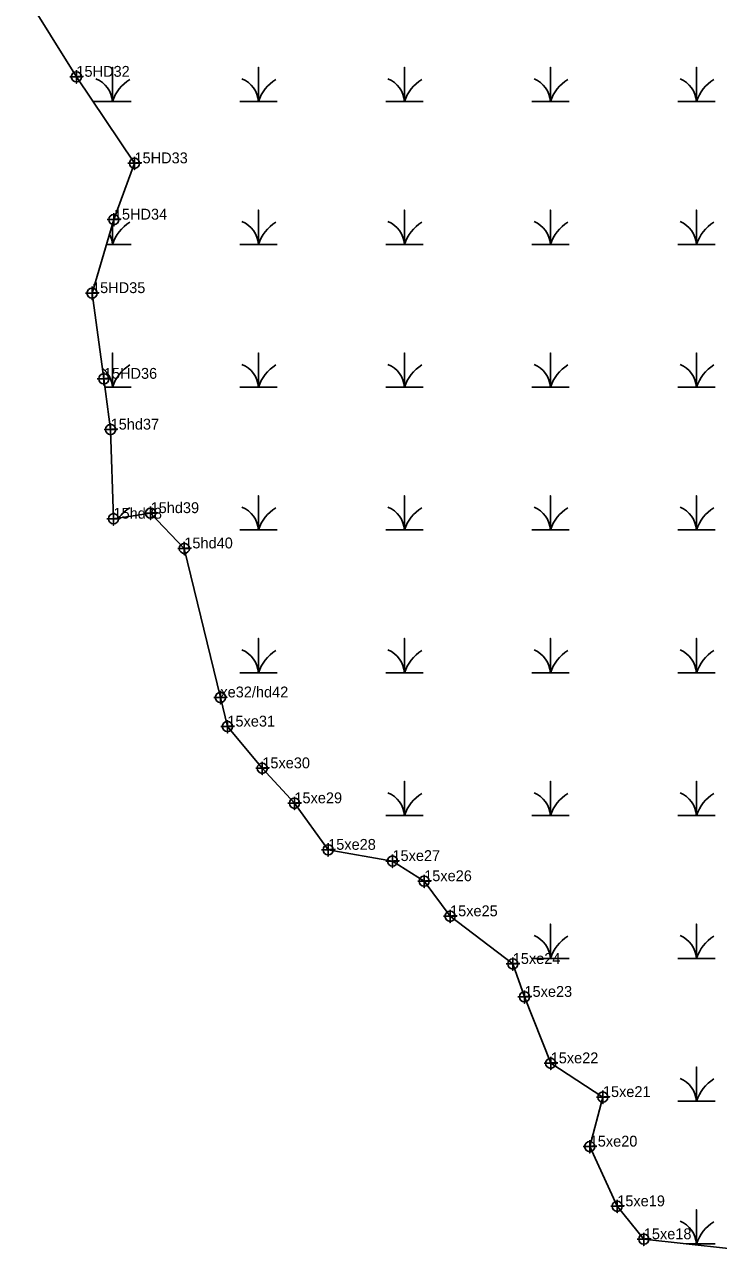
# Model space of a CAD drawing. Extents: x 2071991 to 2268989, y 436479 to 469629.
# Drawn here: x 2267215 to 2267534, y 443490 to 444054 of the extents above; entities that cross this region are included whole.
import ezdxf

# ---------------------------------------------------------------- set-up
doc = ezdxf.new("R2010")
doc.units = 0
for name, color, linetype in [('Exist Environmental Wetland Boundary', 7, 'Continuous'), ('Exist Environmental Wetland Boundary Cogo Comment', 7, 'Continuous'), ('Exist Environmental Wetland Boundary Cogo Point CELL', 7, 'Continuous'), ('Exist Hydro Swamp or Marsh', 7, 'Continuous')]:
    doc.layers.add(name, color=color, linetype=linetype)

msp = doc.modelspace()

# ---------------------------------------------------------------- linework, layer by layer
at = {"layer": 'Exist Environmental Wetland Boundary'}
for points in [[(2267254.71, 443867.46), (2267251.59, 443890.85), (2267246.15, 443930.33), (2267256.19, 443964.18), (2267265.69, 443990.12), (2267238.96, 444029.98), (2267215.07, 444068.53)], [(2267539.01, 443490.2), (2267500.11, 443494.48), (2267487.88, 443509.65), (2267475.21, 443537.15), (2267481.28, 443559.98), (2267457.24, 443575.52), (2267445.19, 443606.13), (2267439.79, 443621.29), (2267410.94, 443643.26), (2267399.03, 443659.42), (2267384.42, 443668.71), (2267354.83, 443673.87), (2267339.3, 443695.32), (2267324.52, 443711.42), (2267308.45, 443730.65), (2267305.23, 443744.08), (2267288.63, 443812.72), (2267273.11, 443828.98), (2267256.02, 443826.4), (2267254.71, 443867.46)]]:
    msp.add_lwpolyline(points, dxfattribs=at)
at = {"layer": 'Exist Environmental Wetland Boundary Cogo Point CELL'}
for points in [[(2267238.96, 444032.98), (2267238.96, 444026.98), (2267238.96, 444029.98), (2267241.96, 444029.98), (2267235.96, 444029.98)], [(2267265.69, 443993.12), (2267265.69, 443987.12), (2267265.69, 443990.12), (2267268.69, 443990.12), (2267262.69, 443990.12)], [(2267256.19, 443967.18), (2267256.19, 443961.18), (2267256.19, 443964.18), (2267259.19, 443964.18), (2267253.19, 443964.18)], [(2267246.15, 443933.33), (2267246.15, 443927.33), (2267246.15, 443930.33), (2267249.15, 443930.33), (2267243.15, 443930.33)], [(2267251.59, 443893.85), (2267251.59, 443887.85), (2267251.59, 443890.85), (2267254.59, 443890.85), (2267248.59, 443890.85)], [(2267254.71, 443870.46), (2267254.71, 443864.46), (2267254.71, 443867.46), (2267257.71, 443867.46), (2267251.71, 443867.46)], [(2267273.11, 443831.98), (2267273.11, 443825.98), (2267273.11, 443828.98), (2267276.11, 443828.98), (2267270.11, 443828.98)], [(2267256.02, 443829.4), (2267256.02, 443823.4), (2267256.02, 443826.4), (2267259.02, 443826.4), (2267253.02, 443826.4)], [(2267288.63, 443815.72), (2267288.63, 443809.72), (2267288.63, 443812.72), (2267291.63, 443812.72), (2267285.63, 443812.72)], [(2267305.23, 443747.08), (2267305.23, 443741.08), (2267305.23, 443744.08), (2267308.23, 443744.08), (2267302.23, 443744.08)], [(2267308.45, 443733.65), (2267308.45, 443727.65), (2267308.45, 443730.65), (2267311.45, 443730.65), (2267305.45, 443730.65)], [(2267324.52, 443714.42), (2267324.52, 443708.42), (2267324.52, 443711.42), (2267327.52, 443711.42), (2267321.52, 443711.42)], [(2267339.3, 443698.32), (2267339.3, 443692.32), (2267339.3, 443695.32), (2267342.3, 443695.32), (2267336.3, 443695.32)], [(2267354.83, 443676.87), (2267354.83, 443670.87), (2267354.83, 443673.87), (2267357.83, 443673.87), (2267351.83, 443673.87)], [(2267384.42, 443671.71), (2267384.42, 443665.71), (2267384.42, 443668.71), (2267387.42, 443668.71), (2267381.42, 443668.71)], [(2267399.03, 443662.42), (2267399.03, 443656.42), (2267399.03, 443659.42), (2267402.03, 443659.42), (2267396.03, 443659.42)], [(2267410.94, 443646.26), (2267410.94, 443640.26), (2267410.94, 443643.26), (2267413.94, 443643.26), (2267407.94, 443643.26)], [(2267439.79, 443624.29), (2267439.79, 443618.29), (2267439.79, 443621.29), (2267442.79, 443621.29), (2267436.79, 443621.29)], [(2267445.19, 443609.13), (2267445.19, 443603.13), (2267445.19, 443606.13), (2267448.19, 443606.13), (2267442.19, 443606.13)], [(2267457.24, 443578.52), (2267457.24, 443572.52), (2267457.24, 443575.52), (2267460.24, 443575.52), (2267454.24, 443575.52)], [(2267481.28, 443562.98), (2267481.28, 443556.98), (2267481.28, 443559.98), (2267484.28, 443559.98), (2267478.28, 443559.98)], [(2267475.21, 443540.15), (2267475.21, 443534.15), (2267475.21, 443537.15), (2267478.21, 443537.15), (2267472.21, 443537.15)], [(2267487.88, 443512.65), (2267487.88, 443506.65), (2267487.88, 443509.65), (2267490.88, 443509.65), (2267484.88, 443509.65)], [(2267500.11, 443497.48), (2267500.11, 443491.48), (2267500.11, 443494.48), (2267503.11, 443494.48), (2267497.11, 443494.48)]]:
    msp.add_lwpolyline(points, dxfattribs=at)
for centre in [(2267238.96, 444029.98), (2267265.69, 443990.12), (2267256.19, 443964.18), (2267246.15, 443930.33), (2267251.59, 443890.85), (2267254.71, 443867.46), (2267273.11, 443828.98), (2267256.02, 443826.4), (2267288.63, 443812.72), (2267305.23, 443744.08), (2267308.45, 443730.65), (2267324.52, 443711.42), (2267339.3, 443695.32), (2267354.83, 443673.87), (2267384.42, 443668.71), (2267399.03, 443659.42), (2267410.94, 443643.26), (2267439.79, 443621.29), (2267445.19, 443606.13), (2267457.24, 443575.52), (2267481.28, 443559.98), (2267475.21, 443537.15), (2267487.88, 443509.65), (2267500.11, 443494.48)]:
    msp.add_circle(centre, 2.34, dxfattribs=at)
at = {"layer": 'Exist Hydro Swamp or Marsh'}
for points in [[(2267246.93, 444018.57), (2267255.53, 444018.57), (2267255.53, 444034.35), (2267255.53, 444018.57), (2267264.13, 444018.57)], [(2267314.13, 444018.57), (2267322.74, 444018.57), (2267322.74, 444034.35), (2267322.74, 444018.57), (2267331.34, 444018.57)], [(2267381.34, 444018.57), (2267389.94, 444018.57), (2267389.94, 444034.35), (2267389.94, 444018.57), (2267398.54, 444018.57)], [(2267448.54, 444018.57), (2267457.14, 444018.57), (2267457.14, 444034.35), (2267457.14, 444018.57), (2267465.74, 444018.57)], [(2267515.74, 444018.57), (2267524.35, 444018.57), (2267524.35, 444034.35), (2267524.35, 444018.57), (2267532.95, 444018.57)], [(2267314.13, 443952.79), (2267322.74, 443952.79), (2267322.74, 443968.57), (2267322.74, 443952.79), (2267331.34, 443952.79)], [(2267381.34, 443952.79), (2267389.94, 443952.79), (2267389.94, 443968.57), (2267389.94, 443952.79), (2267398.54, 443952.79)], [(2267448.54, 443952.79), (2267457.14, 443952.79), (2267457.14, 443968.57), (2267457.14, 443952.79), (2267465.74, 443952.79)], [(2267515.74, 443952.79), (2267524.35, 443952.79), (2267524.35, 443968.57), (2267524.35, 443952.79), (2267532.95, 443952.79)], [(2267252.81, 443952.79), (2267255.53, 443952.79), (2267255.53, 443961.97)], [(2267255.53, 443961.97), (2267255.53, 443952.79), (2267264.13, 443952.79)], [(2267252.1, 443887.01), (2267255.53, 443887.01), (2267255.53, 443902.79), (2267255.53, 443887.01), (2267264.13, 443887.01)], [(2267314.13, 443887.01), (2267322.74, 443887.01), (2267322.74, 443902.79), (2267322.74, 443887.01), (2267331.34, 443887.01)], [(2267381.34, 443887.01), (2267389.94, 443887.01), (2267389.94, 443902.79), (2267389.94, 443887.01), (2267398.54, 443887.01)], [(2267448.54, 443887.01), (2267457.14, 443887.01), (2267457.14, 443902.79), (2267457.14, 443887.01), (2267465.74, 443887.01)], [(2267515.74, 443887.01), (2267524.35, 443887.01), (2267524.35, 443902.79), (2267524.35, 443887.01), (2267532.95, 443887.01)], [(2267314.13, 443821.23), (2267322.74, 443821.23), (2267322.74, 443837.01), (2267322.74, 443821.23), (2267331.34, 443821.23)], [(2267381.34, 443821.23), (2267389.94, 443821.23), (2267389.94, 443837.01), (2267389.94, 443821.23), (2267398.54, 443821.23)], [(2267448.54, 443821.23), (2267457.14, 443821.23), (2267457.14, 443837.01), (2267457.14, 443821.23), (2267465.74, 443821.23)], [(2267515.74, 443821.23), (2267524.35, 443821.23), (2267524.35, 443837.01), (2267524.35, 443821.23), (2267532.95, 443821.23)], [(2267314.13, 443755.45), (2267322.74, 443755.45), (2267322.74, 443771.23), (2267322.74, 443755.45), (2267331.34, 443755.45)], [(2267381.34, 443755.45), (2267389.94, 443755.45), (2267389.94, 443771.23), (2267389.94, 443755.45), (2267398.54, 443755.45)], [(2267448.54, 443755.45), (2267457.14, 443755.45), (2267457.14, 443771.23), (2267457.14, 443755.45), (2267465.74, 443755.45)], [(2267515.74, 443755.45), (2267524.35, 443755.45), (2267524.35, 443771.23), (2267524.35, 443755.45), (2267532.95, 443755.45)], [(2267381.34, 443689.67), (2267389.94, 443689.67), (2267389.94, 443705.45), (2267389.94, 443689.67), (2267398.54, 443689.67)], [(2267448.54, 443689.67), (2267457.14, 443689.67), (2267457.14, 443705.45), (2267457.14, 443689.67), (2267465.74, 443689.67)], [(2267515.74, 443689.67), (2267524.35, 443689.67), (2267524.35, 443705.45), (2267524.35, 443689.67), (2267532.95, 443689.67)], [(2267448.54, 443623.88), (2267457.14, 443623.88), (2267457.14, 443639.67), (2267457.14, 443623.88), (2267465.74, 443623.88)], [(2267515.74, 443623.88), (2267524.35, 443623.88), (2267524.35, 443639.67), (2267524.35, 443623.88), (2267532.95, 443623.88)], [(2267515.74, 443558.1), (2267524.35, 443558.1), (2267524.35, 443573.88), (2267524.35, 443558.1), (2267532.95, 443558.1)], [(2267519.71, 443492.32), (2267524.35, 443492.32), (2267524.35, 443508.1), (2267524.35, 443492.32), (2267532.95, 443492.32)]]:
    msp.add_lwpolyline(points, dxfattribs=at)
for centre, radius, start, end in [((2267243.27, 444017.68), 12.3, 4.1403, 67.535), ((2267273.77, 444012.51), 19.22, 122.1274, 161.6222), ((2267310.47, 444017.68), 12.3, 4.1403, 67.535), ((2267340.98, 444012.51), 19.22, 122.1274, 161.6222), ((2267377.67, 444017.68), 12.3, 4.1403, 67.535), ((2267408.18, 444012.51), 19.22, 122.1274, 161.6222), ((2267444.88, 444017.68), 12.3, 4.1403, 67.535), ((2267475.38, 444012.51), 19.22, 122.1274, 161.6222), ((2267512.08, 444017.68), 12.3, 4.1403, 67.535), ((2267542.59, 444012.51), 19.22, 122.1274, 161.6222), ((2267273.77, 443946.73), 19.22, 122.1274, 161.6222), ((2267310.47, 443951.9), 12.3, 4.1403, 67.535), ((2267340.98, 443946.73), 19.22, 122.1274, 161.6222), ((2267377.67, 443951.9), 12.3, 4.1403, 67.535), ((2267408.18, 443946.73), 19.22, 122.1274, 161.6222), ((2267444.88, 443951.9), 12.3, 4.1403, 67.535), ((2267475.38, 443946.73), 19.22, 122.1274, 161.6222), ((2267512.08, 443951.9), 12.3, 4.1403, 67.535), ((2267542.59, 443946.73), 19.22, 122.1274, 161.6222), ((2267243.27, 443951.9), 12.3, 4.1403, 27.141), ((2267273.77, 443880.95), 19.22, 122.1274, 161.6222), ((2267310.47, 443886.12), 12.3, 4.1403, 67.535), ((2267340.98, 443880.95), 19.22, 122.1274, 161.6222), ((2267377.67, 443886.12), 12.3, 4.1403, 67.535), ((2267408.18, 443880.95), 19.22, 122.1274, 161.6222), ((2267444.88, 443886.12), 12.3, 4.1403, 67.535), ((2267475.38, 443880.95), 19.22, 122.1274, 161.6222), ((2267512.08, 443886.12), 12.3, 4.1403, 67.535), ((2267542.59, 443880.95), 19.22, 122.1274, 161.6222), ((2267243.27, 443886.12), 12.3, 4.1403, 51.5391), ((2267273.77, 443815.17), 19.22, 122.1274, 142.8859), ((2267310.47, 443820.34), 12.3, 4.1403, 67.535), ((2267340.98, 443815.17), 19.22, 122.1274, 161.6222), ((2267377.67, 443820.34), 12.3, 4.1403, 67.535), ((2267408.18, 443815.17), 19.22, 122.1274, 161.6222), ((2267444.88, 443820.34), 12.3, 4.1403, 67.535), ((2267475.38, 443815.17), 19.22, 122.1274, 161.6222), ((2267512.08, 443820.34), 12.3, 4.1403, 67.535), ((2267542.59, 443815.17), 19.22, 122.1274, 161.6222), ((2267310.47, 443754.56), 12.3, 4.1403, 67.535), ((2267340.98, 443749.39), 19.22, 122.1274, 161.6222), ((2267377.67, 443754.56), 12.3, 4.1403, 67.535), ((2267408.18, 443749.39), 19.22, 122.1274, 161.6222), ((2267444.88, 443754.56), 12.3, 4.1403, 67.535), ((2267475.38, 443749.39), 19.22, 122.1274, 161.6222), ((2267512.08, 443754.56), 12.3, 4.1403, 67.535), ((2267542.59, 443749.39), 19.22, 122.1274, 161.6222), ((2267377.67, 443688.78), 12.3, 4.1403, 67.535), ((2267408.18, 443683.6), 19.22, 122.1274, 161.6222), ((2267444.88, 443688.78), 12.3, 4.1403, 67.535), ((2267475.38, 443683.6), 19.22, 122.1274, 161.6222), ((2267512.08, 443688.78), 12.3, 4.1403, 67.535), ((2267542.59, 443683.6), 19.22, 122.1274, 161.6222), ((2267444.88, 443623), 12.3, 4.1403, 67.535), ((2267475.38, 443617.82), 19.22, 122.1274, 161.6222), ((2267512.08, 443623), 12.3, 4.1403, 67.535), ((2267542.59, 443617.82), 19.22, 122.1274, 161.6222), ((2267512.08, 443557.22), 12.3, 4.1403, 67.535), ((2267542.59, 443552.04), 19.22, 122.1274, 161.6222), ((2267512.08, 443491.44), 12.3, 4.1403, 67.535), ((2267542.59, 443486.26), 19.22, 122.1274, 161.6222)]:
    msp.add_arc(centre, radius, start, end, dxfattribs=at)

# ---------------------------------------------------------------- texts
at = {"layer": 'Exist Environmental Wetland Boundary Cogo Comment'}
for s, p in [('15HD32', (2267238.96, 444029.98)), ('15HD33', (2267265.69, 443990.12)), ('15HD34', (2267256.19, 443964.18)), ('15HD35', (2267246.15, 443930.33)), ('15HD36', (2267251.59, 443890.85)), ('15hd37', (2267254.71, 443867.46)), ('15hd38', (2267256.02, 443826.4)), ('15hd39', (2267273.11, 443828.98)), ('15hd40', (2267288.63, 443812.72)), ('xe32/hd42', (2267305.23, 443744.08)), ('15xe31', (2267308.45, 443730.65)), ('15xe30', (2267324.52, 443711.42)), ('15xe29', (2267339.3, 443695.32)), ('15xe28', (2267354.83, 443673.87)), ('15xe27', (2267384.42, 443668.71)), ('15xe26', (2267399.03, 443659.42)), ('15xe25', (2267410.94, 443643.26)), ('15xe24', (2267439.79, 443621.29)), ('15xe23', (2267445.19, 443606.13)), ('15xe22', (2267457.24, 443575.52)), ('15xe21', (2267481.28, 443559.98)), ('15xe20', (2267475.21, 443537.15)), ('15xe19', (2267487.88, 443509.65)), ('15xe18', (2267500.11, 443494.48))]:
    msp.add_text(s, height=5, dxfattribs=at).set_placement(p)

doc.saveas('drawing.dxf')
